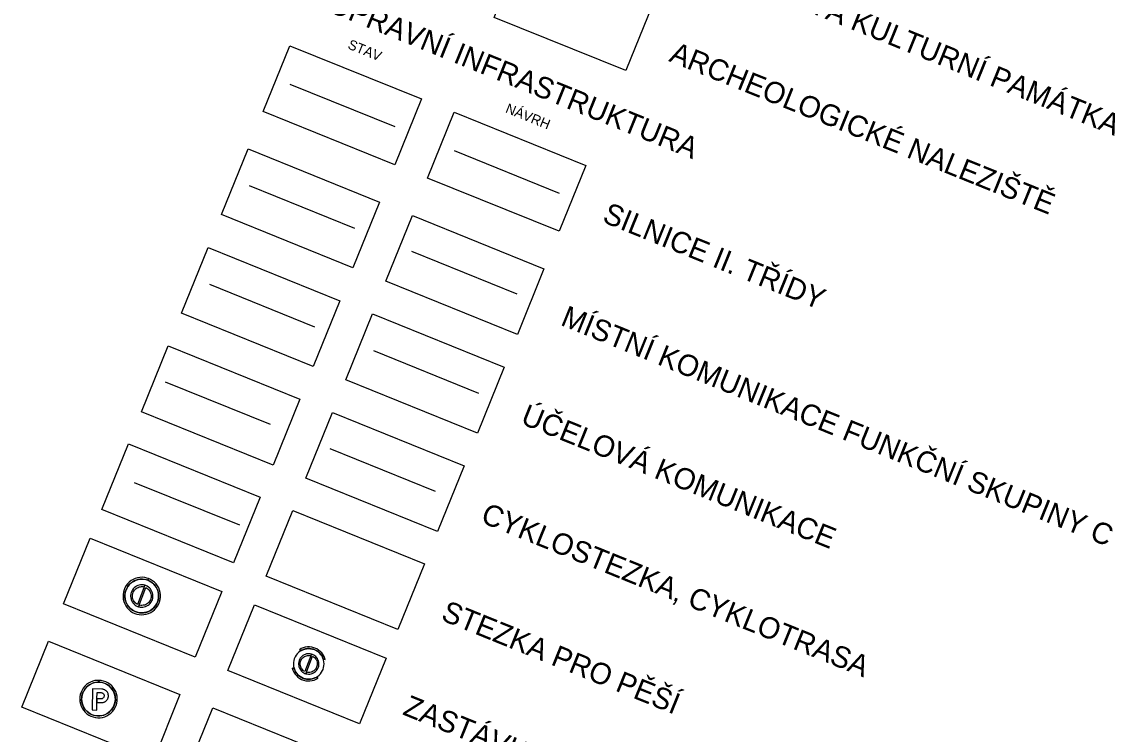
# Model space of a CAD drawing. Extents: x -522754 to -518969, y -1191121 to -1188171.
# Drawn here: x -521824 to -521053, y -1190119 to -1189617 of the extents above; entities that cross this region are included whole.
import ezdxf

# ---------------------------------------------------------------- set-up
doc = ezdxf.new("R2010")
doc.units = 0
for name, color, linetype in [('cyklostezka_s', 7, 'Continuous'), ('DOPRAVA', 7, 'Continuous'), ('Implicitní', 7, 'Continuous'), ('ložisk_nerost', 7, 'Continuous'), ('MK_C_n', 7, 'Continuous'), ('sil_II_n', 7, 'Continuous'), ('stezka_s', 7, 'Continuous'), ('zast_HD_n', 7, 'Continuous'), ('zast_HD_s', 7, 'Continuous')]:
    doc.layers.add(name, color=color, linetype=linetype)

msp = doc.modelspace()

# ---------------------------------------------------------------- linework, layer by layer
at = {"layer": 'cyklostezka_s'}
msp.add_line((-521722.75, -1189870.59), (-521648.6, -1189900.64), dxfattribs=at)
at = {"layer": 'DOPRAVA'}
msp.add_lwpolyline([(-521471.98, -1189567.49), (-521379.27, -1189604.95), (-521398, -1189651.31), (-521490.71, -1189613.85)], close=True, dxfattribs=at)
at = {"layer": 'Implicitní'}
for p, q in [((-521663.39, -1189732.31), (-521589.25, -1189762.36)), ((-521691.56, -1189801.82), (-521617.42, -1189831.86)), ((-521575.97, -1189848.66), (-521501.83, -1189878.71)), ((-521606.56, -1189917.68), (-521532.41, -1189947.73))]:
    msp.add_line(p, q, dxfattribs=at)
for points in [[(-521634.75, -1189633.72), (-521542.07, -1189671.28), (-521560.86, -1189717.62), (-521653.53, -1189680.06)], [(-521518.91, -1189680.67), (-521426.23, -1189718.23), (-521445.01, -1189764.57), (-521537.69, -1189727.01)], [(-521664.21, -1189706.4), (-521571.53, -1189743.96), (-521590.31, -1189790.3), (-521682.99, -1189752.74)], [(-521548.36, -1189753.35), (-521455.69, -1189790.91), (-521474.47, -1189837.25), (-521567.14, -1189799.69)], [(-521692.38, -1189775.91), (-521599.7, -1189813.47), (-521618.48, -1189859.81), (-521711.16, -1189822.25)], [(-521576.53, -1189822.86), (-521483.86, -1189860.42), (-521502.64, -1189906.76), (-521595.31, -1189869.2)], [(-521720.55, -1189845.42), (-521627.87, -1189882.98), (-521646.66, -1189929.32), (-521739.33, -1189891.76)], [(-521604.71, -1189892.37), (-521512.03, -1189929.93), (-521530.81, -1189976.27), (-521623.49, -1189938.71)], [(-521748.5, -1189914.37), (-521655.82, -1189951.94), (-521674.6, -1189998.27), (-521767.28, -1189960.71)], [(-521632.65, -1189961.33), (-521539.97, -1189998.89), (-521558.75, -1190045.23), (-521651.43, -1190007.66)], [(-521775.49, -1189980.97), (-521682.81, -1190018.53), (-521701.59, -1190064.87), (-521794.27, -1190027.31)], [(-521659.64, -1190027.92), (-521566.97, -1190065.49), (-521585.75, -1190111.82), (-521678.42, -1190074.26)], [(-521804.94, -1190053.63), (-521712.26, -1190091.19), (-521731.04, -1190137.53), (-521823.72, -1190099.97)], [(-521689.09, -1190100.58), (-521596.41, -1190138.15), (-521615.19, -1190184.48), (-521707.87, -1190146.92)]]:
    msp.add_lwpolyline(points, close=True, dxfattribs=at)
at = {"layer": 'ložisk_nerost'}
msp.add_line((-521634.91, -1189660.74), (-521560.77, -1189690.79), dxfattribs=at)
for points in [[(-521769.42, -1190081.13), (-521770.52, -1190081.15), (-521772.17, -1190081.36), (-521773.79, -1190081.77), (-521775.34, -1190082.39), (-521776.8, -1190083.2), (-521778.15, -1190084.18), (-521779.36, -1190085.33), (-521780.42, -1190086.62), (-521781.31, -1190088.04), (-521782.01, -1190089.55), (-521782.51, -1190091.15), (-521782.81, -1190092.79), (-521782.9, -1190094.46), (-521782.78, -1190096.12), (-521782.45, -1190097.76), (-521781.92, -1190099.34), (-521781.19, -1190100.84), (-521780.28, -1190102.24), (-521779.19, -1190103.51), (-521777.96, -1190104.64), (-521776.59, -1190105.6), (-521775.12, -1190106.38), (-521773.55, -1190106.97), (-521771.93, -1190107.35), (-521770.27, -1190107.53), (-521768.6, -1190107.5), (-521766.95, -1190107.25), (-521765.34, -1190106.8), (-521763.8, -1190106.15), (-521762.36, -1190105.31), (-521761.03, -1190104.3), (-521759.84, -1190103.13), (-521758.81, -1190101.81), (-521757.95, -1190100.38), (-521757.28, -1190098.85), (-521756.81, -1190097.25), (-521756.55, -1190095.6), (-521756.49, -1190093.93), (-521756.65, -1190092.27), (-521757.01, -1190090.64), (-521757.58, -1190089.07), (-521758.34, -1190087.58), (-521759.29, -1190086.2), (-521760.4, -1190084.95), (-521761.65, -1190083.85), (-521763.04, -1190082.92), (-521764.53, -1190082.18), (-521766.11, -1190081.62), (-521767.74, -1190081.27), (-521769.4, -1190081.13)], [(-521757.81, -1190094.59), (-521757.87, -1190093.09), (-521758.12, -1190091.61), (-521758.56, -1190090.17), (-521759.18, -1190088.8), (-521759.96, -1190087.51), (-521760.9, -1190086.34), (-521761.97, -1190085.29), (-521763.18, -1190084.39), (-521764.48, -1190083.65), (-521765.87, -1190083.08), (-521767.32, -1190082.68), (-521768.81, -1190082.48), (-521770.32, -1190082.46), (-521771.81, -1190082.63), (-521773.27, -1190082.99), (-521774.67, -1190083.53), (-521775.99, -1190084.25), (-521777.22, -1190085.12), (-521778.32, -1190086.15), (-521779.28, -1190087.3), (-521780.09, -1190088.57), (-521780.74, -1190089.92), (-521781.21, -1190091.35), (-521781.49, -1190092.83), (-521781.59, -1190094.33), (-521781.49, -1190095.83), (-521781.21, -1190097.3), (-521780.74, -1190098.73), (-521780.1, -1190100.09), (-521779.29, -1190101.36), (-521778.32, -1190102.51), (-521777.22, -1190103.53), (-521776, -1190104.41), (-521774.68, -1190105.13), (-521773.28, -1190105.67), (-521771.82, -1190106.03), (-521770.33, -1190106.21), (-521768.82, -1190106.19), (-521767.34, -1190105.98), (-521765.88, -1190105.59), (-521764.49, -1190105.02), (-521763.19, -1190104.28), (-521761.98, -1190103.38), (-521760.9, -1190102.33), (-521759.96, -1190101.16), (-521759.18, -1190099.88), (-521758.56, -1190098.51), (-521758.13, -1190097.07), (-521757.87, -1190095.59), (-521757.81, -1190094.59)], [(-521769.43, -1190082.45), (-521768.45, -1190082.51), (-521766.97, -1190082.76), (-521765.53, -1190083.2), (-521764.16, -1190083.81), (-521762.87, -1190084.6), (-521761.7, -1190085.54), (-521760.65, -1190086.62), (-521759.75, -1190087.82), (-521759.01, -1190089.12), (-521758.44, -1190090.52), (-521758.05, -1190091.97), (-521757.84, -1190093.46), (-521757.82, -1190094.96), (-521758, -1190096.45), (-521758.36, -1190097.91), (-521758.9, -1190099.31), (-521759.62, -1190100.63), (-521760.49, -1190101.86), (-521761.51, -1190102.96), (-521762.67, -1190103.92), (-521763.93, -1190104.73), (-521765.29, -1190105.38), (-521766.72, -1190105.84), (-521768.2, -1190106.13), (-521769.7, -1190106.22), (-521771.2, -1190106.13), (-521772.67, -1190105.84), (-521774.1, -1190105.38), (-521775.46, -1190104.73), (-521776.72, -1190103.92), (-521777.88, -1190102.96), (-521778.9, -1190101.86), (-521779.78, -1190100.63), (-521780.49, -1190099.31), (-521781.03, -1190097.91), (-521781.39, -1190096.45), (-521781.57, -1190094.96), (-521781.55, -1190093.46), (-521781.35, -1190091.97), (-521780.95, -1190090.52), (-521780.38, -1190089.13), (-521779.64, -1190087.82), (-521778.74, -1190086.62), (-521777.69, -1190085.54), (-521776.52, -1190084.6), (-521775.24, -1190083.81), (-521773.87, -1190083.2), (-521772.43, -1190082.76), (-521770.95, -1190082.51), (-521769.44, -1190082.45)], [(-521769.44, -1190082.45), (-521769.42, -1190081.13)], [(-521769.4, -1190081.13), (-521769.43, -1190082.45)], [(-521767.37, -1190087.26), (-521773.82, -1190087.12), (-521774.14, -1190102), (-521770.98, -1190102.07), (-521770.81, -1190094.22)], [(-521770.81, -1190094.22), (-521770.71, -1190089.65)], [(-521770.71, -1190089.65), (-521768.13, -1190089.7)], [(-521768.13, -1190089.7), (-521768.01, -1190089.71), (-521767.9, -1190089.71), (-521767.31, -1190089.84), (-521767.08, -1190089.96), (-521766.85, -1190090.08), (-521766.62, -1190090.21), (-521766.39, -1190090.44), (-521766.16, -1190090.68), (-521765.93, -1190091.04), (-521765.82, -1190091.4), (-521765.72, -1190091.98), (-521765.72, -1190092.22), (-521765.85, -1190092.68), (-521765.97, -1190093.03), (-521766.22, -1190093.38), (-521766.34, -1190093.49), (-521766.57, -1190093.72), (-521766.93, -1190093.95), (-521767.17, -1190094.06), (-521767.52, -1190094.17), (-521767.99, -1190094.28), (-521768.23, -1190094.27)], [(-521767.58, -1190096.87), (-521766.88, -1190096.77), (-521766.4, -1190096.66), (-521766.05, -1190096.55), (-521765.7, -1190096.44), (-521765.46, -1190096.33), (-521765.22, -1190096.22), (-521764.87, -1190095.99), (-521764.51, -1190095.76), (-521764.27, -1190095.53), (-521764.03, -1190095.3), (-521763.79, -1190095.07), (-521763.55, -1190094.73), (-521763.31, -1190094.38), (-521763.18, -1190094.15), (-521763.06, -1190093.92), (-521762.94, -1190093.57), (-521762.81, -1190093.22), (-521762.68, -1190092.64), (-521762.68, -1190092.28), (-521762.66, -1190091.81), (-521762.77, -1190091.23), (-521762.77, -1190091.11), (-521762.88, -1190090.75), (-521762.99, -1190090.4), (-521763.21, -1190089.93), (-521763.44, -1190089.57), (-521763.66, -1190089.21), (-521763.89, -1190088.97), (-521764.12, -1190088.73), (-521764.35, -1190088.49), (-521764.7, -1190088.25), (-521765.04, -1190088.01), (-521765.28, -1190087.89), (-521765.51, -1190087.76), (-521765.86, -1190087.64), (-521766.09, -1190087.52), (-521766.67, -1190087.39), (-521767.37, -1190087.26)], [(-521770.76, -1190094.22), (-521770.81, -1190096.8)], [(-521770.81, -1190096.8), (-521767.58, -1190096.87)], [(-521768.23, -1190094.27), (-521770.76, -1190094.22)]]:
    msp.add_lwpolyline(points, dxfattribs=at)
at = {"layer": 'MK_C_n'}
msp.add_line((-521549.05, -1189778.65), (-521474.91, -1189808.7), dxfattribs=at)
at = {"layer": 'sil_II_n'}
msp.add_line((-521519.07, -1189707.7), (-521444.92, -1189737.75), dxfattribs=at)
at = {"layer": 'stezka_s'}
msp.add_line((-521744.54, -1189941.55), (-521670.4, -1189971.6), dxfattribs=at)
at = {"layer": 'zast_HD_n'}
msp.add_line((-521623.51, -1190076.46), (-521623.51, -1190076.46), dxfattribs=at)
for points in [[(-521611.42, -1190073.44), (-521611.01, -1190072.13), (-521610.77, -1190070.79), (-521610.7, -1190069.42), (-521610.81, -1190068.06), (-521611.08, -1190066.72), (-521611.52, -1190065.43), (-521612.12, -1190064.2), (-521612.88, -1190063.06), (-521613.76, -1190062.02), (-521614.78, -1190061.1), (-521615.9, -1190060.32), (-521617.11, -1190059.69), (-521618.39, -1190059.21), (-521619.72, -1190058.9), (-521621.08, -1190058.76), (-521622.44, -1190058.79), (-521623.79, -1190058.99), (-521625.11, -1190059.37), (-521626.37, -1190059.9), (-521627.55, -1190060.59), (-521628.63, -1190061.43), (-521629.6, -1190062.39), (-521630.44, -1190063.47), (-521631.14, -1190064.64), (-521631.68, -1190065.89), (-521632.06, -1190067.21), (-521632.27, -1190068.56), (-521632.31, -1190069.92), (-521632.18, -1190071.28), (-521631.88, -1190072.62), (-521631.41, -1190073.9), (-521630.78, -1190075.11), (-521630.01, -1190076.24), (-521629.1, -1190077.26), (-521628.06, -1190078.15), (-521626.93, -1190078.91), (-521625.7, -1190079.52), (-521624.41, -1190079.97), (-521623.08, -1190080.25), (-521621.71, -1190080.36), (-521620.35, -1190080.3), (-521619, -1190080.07), (-521617.7, -1190079.67), (-521616.45, -1190079.11), (-521615.29, -1190078.39), (-521614.22, -1190077.54), (-521613.27, -1190076.55), (-521612.46, -1190075.46), (-521611.78, -1190074.27), (-521611.42, -1190073.44)], [(-521617.22, -1190058.34), (-521617.92, -1190058.1), (-521619.4, -1190057.74), (-521620.91, -1190057.56), (-521622.43, -1190057.58), (-521623.93, -1190057.79), (-521625.39, -1190058.19), (-521626.8, -1190058.77), (-521628.12, -1190059.52)], [(-521628.12, -1190059.52), (-521626.7, -1190060.07)], [(-521626.7, -1190060.07), (-521625.66, -1190059.57), (-521624.36, -1190059.13), (-521623.02, -1190058.85), (-521621.66, -1190058.75), (-521620.3, -1190058.82), (-521618.95, -1190059.06), (-521617.65, -1190059.46)], [(-521617.64, -1190059.47), (-521616.59, -1190059.94), (-521615.41, -1190060.64), (-521614.34, -1190061.48), (-521613.37, -1190062.45), (-521612.54, -1190063.54), (-521611.86, -1190064.72), (-521611.32, -1190065.97)], [(-521609.9, -1190066.52), (-521610.11, -1190065.8), (-521610.68, -1190064.39), (-521611.42, -1190063.07), (-521612.32, -1190061.84), (-521613.36, -1190060.74), (-521614.54, -1190059.78), (-521615.83, -1190058.98), (-521617.21, -1190058.35)], [(-521619.53, -1190062.65), (-521620.42, -1190062.45), (-521621.32, -1190062.37), (-521622.23, -1190062.4), (-521623.13, -1190062.55), (-521624, -1190062.81), (-521624.83, -1190063.18), (-521625.61, -1190063.64), (-521626.32, -1190064.21), (-521626.96, -1190064.86), (-521627.51, -1190065.58), (-521627.96, -1190066.37), (-521628.31, -1190067.21), (-521628.56, -1190068.08), (-521628.68, -1190068.98), (-521628.7, -1190069.89), (-521628.6, -1190070.79), (-521628.39, -1190071.68), (-521628.06, -1190072.53), (-521627.64, -1190073.33), (-521627.11, -1190074.07), (-521626.5, -1190074.74), (-521625.8, -1190075.32), (-521625.04, -1190075.82), (-521624.22, -1190076.21), (-521623.55, -1190076.45)], [(-521624.21, -1190074.96), (-521624.87, -1190074.57), (-521625.48, -1190074.11), (-521626.02, -1190073.57), (-521626.5, -1190072.98), (-521626.89, -1190072.32), (-521627.19, -1190071.62), (-521627.41, -1190070.89), (-521627.53, -1190070.13), (-521627.55, -1190069.37), (-521627.48, -1190068.61), (-521627.32, -1190067.87), (-521627.06, -1190067.15), (-521626.71, -1190066.47), (-521626.28, -1190065.84), (-521625.77, -1190065.27), (-521625.2, -1190064.77), (-521624.56, -1190064.34), (-521623.88, -1190064), (-521623.16, -1190063.74), (-521622.42, -1190063.58), (-521621.65, -1190063.52), (-521620.89, -1190063.55), (-521620.14, -1190063.68), (-521619.95, -1190063.73)], [(-521619.49, -1190062.66), (-521624.21, -1190074.96)], [(-521623.55, -1190076.45), (-521618.83, -1190064.15)], [(-521623.51, -1190076.46), (-521622.62, -1190076.66), (-521621.72, -1190076.74), (-521620.81, -1190076.71), (-521619.91, -1190076.56), (-521619.04, -1190076.3), (-521618.21, -1190075.93), (-521617.43, -1190075.46), (-521616.72, -1190074.9), (-521616.08, -1190074.25), (-521615.53, -1190073.53), (-521615.08, -1190072.74), (-521614.73, -1190071.9), (-521614.49, -1190071.03), (-521614.36, -1190070.13), (-521614.34, -1190069.22), (-521614.44, -1190068.32), (-521614.65, -1190067.43), (-521614.98, -1190066.58), (-521615.4, -1190065.78), (-521615.93, -1190065.04), (-521616.54, -1190064.37), (-521617.24, -1190063.78), (-521618, -1190063.29), (-521618.82, -1190062.89), (-521619.49, -1190062.66)], [(-521618.83, -1190064.15), (-521618.17, -1190064.53), (-521617.56, -1190065), (-521617.02, -1190065.53), (-521616.54, -1190066.13), (-521616.15, -1190066.79), (-521615.85, -1190067.49), (-521615.63, -1190068.22), (-521615.51, -1190068.97), (-521615.49, -1190069.73), (-521615.56, -1190070.5), (-521615.72, -1190071.24), (-521615.98, -1190071.96), (-521616.33, -1190072.64), (-521616.76, -1190073.27), (-521617.27, -1190073.84), (-521617.84, -1190074.34), (-521618.48, -1190074.77), (-521619.16, -1190075.11), (-521619.88, -1190075.36), (-521620.62, -1190075.52), (-521621.38, -1190075.59), (-521622.15, -1190075.56), (-521622.9, -1190075.43), (-521623.09, -1190075.38)], [(-521619.95, -1190063.73), (-521619.53, -1190062.65)], [(-521611.32, -1190065.97), (-521609.9, -1190066.52)], [(-521633.14, -1190072.59), (-521632.67, -1190074.02), (-521632.01, -1190075.39), (-521631.19, -1190076.67), (-521630.22, -1190077.83), (-521629.1, -1190078.86), (-521627.87, -1190079.75), (-521626.53, -1190080.47), (-521625.12, -1190081.01), (-521623.64, -1190081.37), (-521622.13, -1190081.55), (-521620.62, -1190081.53), (-521619.11, -1190081.32), (-521617.65, -1190080.92), (-521616.24, -1190080.34), (-521614.93, -1190079.59)], [(-521631.72, -1190073.13), (-521633.14, -1190072.59)], [(-521616.35, -1190079.04), (-521617.2, -1190079.46), (-521618.48, -1190079.93), (-521619.82, -1190080.23), (-521621.18, -1190080.36), (-521622.54, -1190080.31), (-521623.89, -1190080.1), (-521625.2, -1190079.72), (-521626.45, -1190079.17), (-521627.63, -1190078.47), (-521628.7, -1190077.63), (-521629.67, -1190076.66), (-521630.5, -1190075.57), (-521631.19, -1190074.39), (-521631.72, -1190073.13)], [(-521623.09, -1190075.38), (-521623.51, -1190076.46)], [(-521614.93, -1190079.59), (-521616.35, -1190079.04)]]:
    msp.add_lwpolyline(points, dxfattribs=at)
at = {"layer": 'zast_HD_s'}
msp.add_line((-521741.38, -1190029.29), (-521741.38, -1190029.29), dxfattribs=at)
for points in [[(-521734.48, -1190009.35), (-521735.53, -1190009), (-521737.15, -1190008.64), (-521738.82, -1190008.48), (-521740.49, -1190008.54), (-521742.14, -1190008.81), (-521743.74, -1190009.28), (-521745.27, -1190009.95), (-521746.7, -1190010.81), (-521748.01, -1190011.84), (-521749.18, -1190013.03), (-521750.19, -1190014.36), (-521751.03, -1190015.81), (-521751.68, -1190017.34), (-521752.13, -1190018.95), (-521752.37, -1190020.61), (-521752.4, -1190022.28), (-521752.22, -1190023.94), (-521751.83, -1190025.56), (-521751.24, -1190027.12), (-521750.46, -1190028.6), (-521749.5, -1190029.96), (-521748.37, -1190031.2), (-521747.1, -1190032.28), (-521745.7, -1190033.19), (-521744.2, -1190033.92), (-521742.61, -1190034.45), (-521740.97, -1190034.78), (-521739.31, -1190034.89), (-521737.64, -1190034.8), (-521736, -1190034.5), (-521734.41, -1190033.99), (-521732.89, -1190033.29), (-521731.48, -1190032.4), (-521730.19, -1190031.34), (-521729.04, -1190030.13), (-521728.06, -1190028.78), (-521727.25, -1190027.31), (-521726.64, -1190025.76), (-521726.22, -1190024.14), (-521726.02, -1190022.49), (-521726.02, -1190020.82), (-521726.24, -1190019.16), (-521726.66, -1190017.55), (-521727.28, -1190016), (-521728.1, -1190014.54), (-521729.09, -1190013.19), (-521730.24, -1190011.98), (-521731.54, -1190010.93), (-521732.95, -1190010.05), (-521734.47, -1190009.35)], [(-521728.1, -1190025.94), (-521727.65, -1190024.51), (-521727.39, -1190023.03), (-521727.32, -1190021.52), (-521727.43, -1190020.03), (-521727.73, -1190018.55), (-521728.22, -1190017.13), (-521728.88, -1190015.78), (-521729.71, -1190014.53), (-521730.69, -1190013.39), (-521731.81, -1190012.38), (-521733.04, -1190011.52), (-521734.37, -1190010.82), (-521735.78, -1190010.3), (-521737.24, -1190009.96), (-521738.74, -1190009.81), (-521740.24, -1190009.84), (-521741.73, -1190010.07), (-521743.17, -1190010.48), (-521744.56, -1190011.07), (-521745.85, -1190011.83), (-521747.04, -1190012.75), (-521748.11, -1190013.81), (-521749.03, -1190015), (-521749.8, -1190016.29), (-521750.39, -1190017.67), (-521750.81, -1190019.11), (-521751.04, -1190020.6), (-521751.09, -1190022.1), (-521750.94, -1190023.6), (-521750.6, -1190025.06), (-521750.09, -1190026.47), (-521749.4, -1190027.81), (-521748.54, -1190029.05), (-521747.54, -1190030.16), (-521746.4, -1190031.15), (-521745.15, -1190031.98), (-521743.8, -1190032.65), (-521742.38, -1190033.14), (-521740.91, -1190033.45), (-521739.41, -1190033.57), (-521737.91, -1190033.5), (-521736.43, -1190033.25), (-521735, -1190032.81), (-521733.63, -1190032.19), (-521732.35, -1190031.4), (-521731.18, -1190030.46), (-521730.13, -1190029.37), (-521729.24, -1190028.17), (-521728.5, -1190026.86), (-521728.1, -1190025.94)], [(-521734.94, -1190010.59), (-521734.04, -1190010.98), (-521732.73, -1190011.72), (-521731.52, -1190012.61), (-521730.44, -1190013.65), (-521729.49, -1190014.82), (-521728.71, -1190016.1), (-521728.09, -1190017.47), (-521727.64, -1190018.91), (-521727.39, -1190020.39), (-521727.32, -1190021.89), (-521727.44, -1190023.39), (-521727.75, -1190024.86), (-521728.24, -1190026.28), (-521728.91, -1190027.63), (-521729.74, -1190028.88), (-521730.72, -1190030.02), (-521731.84, -1190031.02), (-521733.08, -1190031.88), (-521734.41, -1190032.57), (-521735.82, -1190033.08), (-521737.29, -1190033.42), (-521738.78, -1190033.57), (-521740.29, -1190033.53), (-521741.77, -1190033.29), (-521743.22, -1190032.88), (-521744.6, -1190032.28), (-521745.89, -1190031.52), (-521747.08, -1190030.59), (-521748.14, -1190029.53), (-521749.06, -1190028.34), (-521749.82, -1190027.04), (-521750.41, -1190025.66), (-521750.82, -1190024.22), (-521751.05, -1190022.73), (-521751.08, -1190021.23), (-521750.93, -1190019.73), (-521750.59, -1190018.27), (-521750.07, -1190016.86), (-521749.37, -1190015.53), (-521748.51, -1190014.29), (-521747.51, -1190013.18), (-521746.37, -1190012.2), (-521745.11, -1190011.37), (-521743.76, -1190010.71), (-521742.34, -1190010.22), (-521740.87, -1190009.91), (-521739.37, -1190009.8), (-521737.87, -1190009.87), (-521736.39, -1190010.14), (-521734.95, -1190010.58)], [(-521737.02, -1190014.09), (-521738, -1190013.87), (-521739, -1190013.78), (-521740, -1190013.82), (-521740.98, -1190013.98), (-521741.94, -1190014.27), (-521742.85, -1190014.67), (-521743.71, -1190015.19), (-521744.49, -1190015.81), (-521745.19, -1190016.53), (-521745.8, -1190017.32), (-521746.29, -1190018.19), (-521746.68, -1190019.11), (-521746.94, -1190020.08), (-521747.08, -1190021.06), (-521747.1, -1190022.06), (-521746.99, -1190023.06), (-521746.75, -1190024.03), (-521746.4, -1190024.96), (-521745.93, -1190025.84), (-521745.35, -1190026.66), (-521744.67, -1190027.39), (-521743.91, -1190028.04), (-521743.07, -1190028.58), (-521742.17, -1190029.02), (-521741.43, -1190029.27)], [(-521742.16, -1190027.63), (-521742.89, -1190027.21), (-521743.55, -1190026.7), (-521744.15, -1190026.11), (-521744.67, -1190025.46), (-521745.1, -1190024.74), (-521745.44, -1190023.97), (-521745.68, -1190023.16), (-521745.81, -1190022.33), (-521745.84, -1190021.49), (-521745.76, -1190020.66), (-521745.58, -1190019.84), (-521745.3, -1190019.05), (-521744.91, -1190018.3), (-521744.44, -1190017.61), (-521743.89, -1190016.98), (-521743.26, -1190016.42), (-521742.56, -1190015.96), (-521741.81, -1190015.58), (-521741.02, -1190015.3), (-521740.2, -1190015.12), (-521739.36, -1190015.05), (-521738.52, -1190015.08), (-521737.69, -1190015.22), (-521737.48, -1190015.27)], [(-521736.97, -1190014.1), (-521742.16, -1190027.63)], [(-521741.43, -1190029.27), (-521736.25, -1190015.74)], [(-521741.38, -1190029.29), (-521740.4, -1190029.5), (-521739.41, -1190029.59), (-521738.41, -1190029.55), (-521737.42, -1190029.39), (-521736.47, -1190029.1), (-521735.55, -1190028.7), (-521734.7, -1190028.18), (-521733.91, -1190027.56), (-521733.21, -1190026.85), (-521732.61, -1190026.05), (-521732.11, -1190025.18), (-521731.73, -1190024.26), (-521731.46, -1190023.3), (-521731.32, -1190022.31), (-521731.31, -1190021.31), (-521731.42, -1190020.32), (-521731.65, -1190019.34), (-521732.01, -1190018.41), (-521732.48, -1190017.53), (-521733.06, -1190016.71), (-521733.73, -1190015.98), (-521734.5, -1190015.33), (-521735.34, -1190014.79), (-521736.24, -1190014.36), (-521736.97, -1190014.1)], [(-521736.25, -1190015.74), (-521735.52, -1190016.16), (-521734.85, -1190016.67), (-521734.25, -1190017.26), (-521733.73, -1190017.92), (-521733.3, -1190018.64), (-521732.97, -1190019.41), (-521732.73, -1190020.21), (-521732.59, -1190021.04), (-521732.56, -1190021.88), (-521732.64, -1190022.72), (-521732.83, -1190023.53), (-521733.11, -1190024.33), (-521733.49, -1190025.07), (-521733.96, -1190025.77), (-521734.52, -1190026.39), (-521735.15, -1190026.95), (-521735.85, -1190027.42), (-521736.6, -1190027.8), (-521737.39, -1190028.08), (-521738.21, -1190028.25), (-521739.05, -1190028.33), (-521739.89, -1190028.29), (-521740.71, -1190028.15), (-521740.93, -1190028.1)], [(-521737.48, -1190015.27), (-521737.02, -1190014.09)], [(-521734.95, -1190010.58), (-521734.48, -1190009.35)], [(-521734.47, -1190009.35), (-521734.94, -1190010.59)], [(-521740.93, -1190028.1), (-521741.38, -1190029.29)]]:
    msp.add_lwpolyline(points, dxfattribs=at)

# ---------------------------------------------------------------- texts
at = {"layer": 'DOPRAVA'}
for s, rotation, p in [('NEMOVITÁ KULTURNÍ PAMÁTKA', 337.93806, (-521342.77, -1189580.14)), ('ARCHEOLOGICKÉ NALEZIŠTĚ', 337.9995, (-521368.26, -1189644.45))]:
    msp.add_text(s, height=15, rotation=rotation, dxfattribs=at).set_placement(p)
at = {"layer": 'Implicitní'}
for s, height, p in [('DOPRAVNÍ INFRASTRUKTURA', 15, (-521622.58, -1189603.69)), ('STAV', 7, (-521594.55, -1189635.55)), ('NÁVRH', 7, (-521483.4, -1189680.6)), ('SILNICE II. TŘÍDY', 15, (-521415.27, -1189757.74)), ('MÍSTNÍ KOMUNIKACE FUNKČNÍ SKUPINY C', 15, (-521444.72, -1189830.43)), ('ÚČELOVÁ KOMUNIKACE', 15, (-521472.89, -1189899.93)), ('CYKLOSTEZKA, CYKLOTRASA ', 15, (-521501.07, -1189969.44)), ('STEZKA PRO PĚŠÍ', 15, (-521529.01, -1190038.4)), ('ZASTÁVKA HROMADNÉ DOPRAVY OSOB', 15, (-521556, -1190105))]:
    msp.add_text(s, height=height, rotation=337.93793, dxfattribs=at).set_placement(p)

doc.saveas('drawing.dxf')
